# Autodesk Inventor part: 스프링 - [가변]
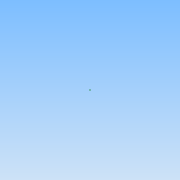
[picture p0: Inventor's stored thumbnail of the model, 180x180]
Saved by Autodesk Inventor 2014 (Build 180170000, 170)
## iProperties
Created: 2015-04
Part Number: 스프링 - [가변]
Material: Generic
Document SubType Name: Modeling
Designer: Administrator
Density: 1 g/cm^3
Appearance: Default
Mass: 0.620006 g
Surface Area: 12.6425 cm^2
Volume: 0.620006 cm^3
Author: Administrator
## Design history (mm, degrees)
sketch "스케치1"
  geometry: L1 (0, 0)-(8, 0); L2 (8, 0)-(8, 24.5); L3 (8, 24.5)-(0, 24.5); L4 (0, 24.5)-(0, 0); C1 r 1 at (8, 0)
  constraints: 8 end point, 2 parallel, 1 centre point, 1 coincident, 1 horizontal, 1 perpendicular
  dimensions: "d0" = 16 diameter of L2 L4; "d1" = 24.49951 distance between parallel lines of L1 L3 (derived); "d2" = 2 diameter of C1
feature "코일1" pitch "d3" = 10; turns "d5" = 4; dims "d4" = 24.49951 (= d1), "d6" = 0, angle "d7" = 90 deg, angle "d8" = 90 deg, "d9" = 0, "d10" = 0
sketch "스케치2"
  geometry: L1 (-9, 0)-(-7, 0) reference; 1 further point
  constraints: 1 horizontal alignment
extrude "돌출1" cut sketch "스케치2" stored distance "d11" = 10; taper "d12" = 0 deg
node "작업 평면1"
sketch "스케치3"
  geometry: L1 (9, 0)-(7, 0) reference; 1 further point
  constraints: 1 horizontal alignment
extrude "돌출2" cut sketch "스케치3" stored distance "d13" = 10; taper "d14" = 0 deg
node "솔리드1"
node "절단 모서리 투영1"
node "절단 모서리 투영2"
